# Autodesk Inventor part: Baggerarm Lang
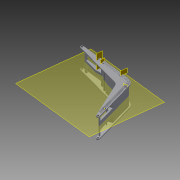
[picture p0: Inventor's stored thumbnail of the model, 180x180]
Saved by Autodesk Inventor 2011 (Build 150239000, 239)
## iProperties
Created: 2011-06
Part Number: Baggerarm Lang
Document SubType Name: Modeling
Designer: Splendor
Density: 1 g/cm^3
Author: Splendor
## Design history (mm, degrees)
sketch "Skizze1"
  geometry: L1 (-226.92, -104.915)-(-3257.541, 6449.975); L2 (240.687, 67.601)-(-1916.665, 7748.673); L3 (-3149.923, 8798.534)-(-12577.464, 9873.179); L4 (-12671.494, 9383.579)-(-3901.21, 6994.175); A1 r 250 centre (0, 0) between (-226.92, -104.915) and (240.687, 67.601); A2 r 1451.763 centre (-3314.345, 7356.112) between (-1916.665, 7748.673) and (-3149.923, 8798.534); A3 r 250 centre (-12605.778, 9624.788) between (-12577.464, 9873.179) and (-12671.494, 9383.579); A4 r 998.218 centre (-4163.604, 6031.061) between (-3257.541, 6449.975) and (-3901.21, 6994.175); 1 further point
  constraints: 8 end point, 8 point on circle, 8 tangent, 4 centre point, 1 coincident
  dimensions: "d0" = 500 diameter of A1; "d1" = 500 diameter of A3
extrude "Extrusion1" new body sketch "Skizze1" distance "d2" = 200; taper "d3" = 0 deg
sketch "Skizze2"
  geometry: C1 r 175 at (-12605.778, 9624.788); C2 r 175 at (0, 0); A1 r 250 centre (0, 0) between (-226.92, -104.915) and (240.687, 67.601) reference; A2 r 250 centre (-12605.778, 9624.788) between (-12577.464, 9873.179) and (-12671.494, 9383.579) reference
  constraints: 2 centre point, 2 coincident
  dimensions: "d5" = 350 diameter of C1; "d6" = 350 diameter of C2
extrude "Extrusion2" cut sketch "Skizze2" stored distance "d7" = 200; taper "d8" = 0 deg
workplane "Arbeitsebene1"
mirror "Spiegeln1"
sketch "Skizze3"
  geometry: L1 (-3912.57, -8515.113)-(-159.064, -2345.636) reference; L2 (542.098, -1877.837)-(9526.566, -497.099) reference; L3 (-1344.227, -903.431)-(-4357.63, -8290.747) reference; L4 (8690.156, -200)-(0, -200); L5 (-159.064, -2345.636)-(-3912.57, -8515.113) reference; L6 (9526.566, -497.099)-(542.098, -1877.837) reference; L7 (0, 0)-(9488.592, 0) reference; L8 (-4357.63, -8290.747)-(-1344.227, -903.431) reference; L9 (-1159.042, -978.971)-(-4022.549, -7998.821); L10 (1246.9, -1564.457)-(906.372, -1616.79); L11 (3330.231, -1244.29)-(3545.266, -575.476); L12 (3599.295, -541.195)-(5980.725, -849.981); L13 (1246.9, -1564.457)-(3330.231, -1244.29); L14 (5980.725, -849.981)-(8709.257, -430.658); L15 (-2274.818, -5428.132)-(-2678.095, -5465.687); L16 (-2763.514, -5533.108)-(-3307.777, -7136.248); L17 (-538.042, -2573.468)-(-2274.818, -5428.132); L18 (-3307.777, -7136.248)-(-3878.853, -8074.901); C1 r 175 at (-4126.148, -8385.172) reference; C2 r 175 at (9488.592, -250) reference; A1 r 250 centre (-4126.148, -8385.172) between (-4357.63, -8290.747) and (-3912.57, -8515.113) reference; A2 r 998.218 centre (693.724, -2864.472) between (542.098, -1877.837) and (-159.064, -2345.636) reference; A3 r 250 centre (9488.592, -250) between (9526.566, -497.099) and (9488.592, 0) reference; A4 r 1451.763 centre (0, -1451.763) between (0, 0) and (-1344.227, -903.431) reference; A5 r 1251.763 centre (0, -1451.763) between (0, -200) and (-1159.042, -978.971); A6 r 1265.674 centre (693.724, -2864.472) between (906.372, -1616.79) and (-538.042, -2573.468); A7 r 800 centre (9488.592, -250) between (8690.156, -200) and (8709.257, -430.658); A8 r 400 centre (-4126.148, -8385.172) between (-3877.158, -8072.116) and (-4022.549, -7998.821); A9 r 50 centre (3592.866, -590.78) between (3599.295, -541.195) and (3545.266, -575.476); A10 r 100 centre (-2668.823, -5565.256) between (-2678.095, -5465.687) and (-2763.514, -5533.108)
  constraints: 22 end point, 12 point on circle, 7 parallel, 6 centre point, 5 tangent, 4 coincident, 1 collinear, 1 point on line
  dimensions: "d12" = 200 distance between parallel lines of L7 L4; "d13" = 200 distance between parallel lines of L9 L8; "d16" = 800 radius of A7; "d18" = 100 diameter of A9; "d19" = 200 diameter of A10
extrude "Extrusion3" join sketch "Skizze3" stored distance "d20" = 0; taper "d21" = 0 deg
sketch "Skizze4"
  geometry: L1 (5980.725, -849.981)-(3599.295, -541.195) reference; L2 (3545.266, -575.476)-(3330.231, -1244.29) reference; C1 r 150 at (3805.463, -976.537)
  constraints: 1 centre point
  dimensions: "d22" = 300 diameter of C1
extrude "Extrusion4" join sketch "Skizze4" stored distance "d23" = 200; taper "d24" = 0 deg
sketch "Skizze5"
  geometry: C1 r 75 at (-2558.636, -5694.936)
  constraints: 1 centre point
  dimensions: "d25" = 150 diameter of C1
extrude "Extrusion5" join sketch "Skizze5" stored distance "d26" = 200; taper "d27" = 0 deg
sketch "Skizze6"
  geometry: L1 (0, -7581.422)-(3400, -7581.422) reference; L2 (3400, -7581.422)-(2400, -7581.422); L3 (2400, -7581.422)-(2400, -4081.422); L4 (2400, -4081.422)-(3400, -4081.422); L5 (3400, -4081.422)-(3400, -7581.422); L6 (0, -7581.422)-(1000, -7581.422); L7 (1000, -7581.422)-(1000, -4081.422); L8 (1000, -4081.422)-(0, -4081.422); L9 (0, -4081.422)-(0, -7581.422); 1 further point
  constraints: 16 end point, 4 parallel, 2 horizontal, 2 perpendicular
  dimensions: "d28" = 1000 distance of L7.end L8.end; "d29" = 1000 distance of L3.end L4.end; "d30" = 3500 distance between parallel lines of L1 L8; "d31" = 3500 distance of L2.end L3.end
extrude "Extrusion6" cut sketch "Skizze6" stored distance "d32" = 10; taper "d33" = 0 deg
sketch "Skizze7"
  geometry: L1 (0, 3400)-(3800, 3400); L2 (3800, 3400)-(3800, 2100); L3 (3800, 2100)-(0, 2100); L4 (0, 2100)-(0, 3400); L5 (0, 0)-(3800, 0); L6 (3800, 0)-(3800, 1300); L7 (3800, 1300)-(0, 1300); L8 (0, 1300)-(0, 0); 1 further point
  constraints: 16 end point, 4 parallel, 2 horizontal, 2 perpendicular
  dimensions: "d34" = 1300 distance of L1.end L2.end; "d35" = 1300 distance of L5.end L6.end; "d36" = 3800 distance of L2.end L3.end; "d37" = 3800 distance of L6.end L7.end
extrude "Extrusion7" cut sketch "Skizze7" stored distance "d38" = 10; taper "d39" = 0 deg
sketch "Skizze8"
  geometry: L1 (-155.45, 368.558)-(-217.437, 351.148) reference; L2 (-671.657, 1333.574)-(-217.437, 351.148) reference; L3 (-1030.851, 2988.04)-(-671.657, 1333.574) reference; L4 (-1504.514, 3147.69)-(-1108.085, 3064.702) reference; L5 (-1699.867, 3570.214)-(-1504.514, 3147.69) reference; L6 (-1005.586, 3765.214)-(-1699.867, 3570.214) reference; L7 (-59.175, 395.599)-(-1005.586, 3765.214) reference; L8 (-211.932, 339.241)-(-275.382, 476.476); L9 (-59.175, 395.599)-(-100.058, 541.159); A1 r 400 centre (0, 0) between (-155.45, 368.558) and (-211.932, 339.241) reference; A2 r 400 centre (0, 0) between (-59.175, 395.599) and (-211.932, 339.241); A3 r 550.332 centre (0, 0) between (-100.058, 541.159) and (-275.382, 476.476); A4 r 400 centre (0, 0) between (-59.175, 395.599) and (-155.45, 368.558) reference; A5 r 100 centre (-1128.575, 2966.824) between (-1030.851, 2988.04) and (-1108.085, 3064.702) reference
  constraints: 5 point on circle, 4 end point, 4 point on line, 2 centre point, 2 coincident
extrude "Extrusion8" join sketch "Skizze8" stored distance "d40" = 10; taper "d41" = 0 deg
sketch "Skizze9"
  geometry: L1 (-8031.267, 9153.663)-(-11806.816, 9584.038) reference; L2 (-8031.267, 9153.663)-(-8088.866, 8648.362) reference; L3 (-9188.433, 8631.378)-(-8088.866, 8648.362) reference; L4 (-11833.273, 9351.947)-(-9188.433, 8631.378) reference; L5 (-11818.142, 9484.681)-(-11833.273, 9351.947) reference; L6 (-11851.918, 9357.027)-(-11496.339, 9260.152); L7 (-11806.816, 9584.038)-(-11440.869, 9542.324); A1 r 800 centre (-12605.778, 9624.788) between (-11818.142, 9484.681) and (-11806.816, 9584.038) reference; A2 r 800 centre (-12605.778, 9624.788) between (-11851.918, 9357.027) and (-11806.816, 9584.038); A3 r 1167.824 centre (-12605.778, 9624.788) between (-11496.339, 9260.152) and (-11440.869, 9542.324)
  constraints: 4 end point, 4 point on circle, 4 point on line, 2 centre point, 2 coincident, 1 concentric
extrude "Extrusion9" join sketch "Skizze9" stored distance "d42" = 10; taper "d43" = 0 deg
workplane "Arbeitsebene2"
sketch "Skizze12"
  geometry: L1 (13846.222, -8290.747)-(10832.82, -903.431) reference; L2 (9488.592, 0)-(0, 0) reference; L3 (-37.974, -497.099)-(8946.495, -1877.837) reference; L4 (9647.657, -2345.636)-(13401.163, -8515.113) reference; L5 (3651.387, -150)-(9488.592, -150); L6 (3651.387, -300)-(9488.592, -300); L7 (3651.387, -450)-(9488.592, -450); L8 (13481.501, -7793.778)-(10693.93, -960.086); L9 (13342.612, -7850.433)-(10555.041, -1016.741); L10 (13203.723, -7907.088)-(10416.152, -1073.396); L11 (12882.87, -8037.969)-(14197.995, -7501.508); C1 r 175 at (13614.74, -8385.172) reference; C2 r 175 at (0, -250) reference; A1 r 250 centre (13614.74, -8385.172) between (13401.163, -8515.113) and (13846.222, -8290.747) reference; A2 r 1451.763 centre (9488.592, -1451.763) between (10832.82, -903.431) and (9488.592, 0) reference; A3 r 250 centre (0, -250) between (0, 0) and (-37.974, -497.099) reference; A4 r 998.218 centre (8794.868, -2864.472) between (9647.657, -2345.636) and (8946.495, -1877.837) reference; A5 r 1301.763 centre (9488.592, -1451.763) between (10693.93, -960.086) and (9488.592, -150); A6 r 1151.763 centre (9488.592, -1451.763) between (10555.041, -1016.741) and (9488.592, -300); A7 r 1001.763 centre (9488.592, -1451.763) between (10416.152, -1073.396) and (9488.592, -450); 1 further point
  constraints: 14 end point, 6 parallel, 6 point on circle, 6 tangent, 3 centre point, 3 coincident, 3 point on line, 1 perpendicular
  dimensions: "d49" = 150 distance between parallel lines of L2 L5; "d50" = 150 distance between parallel lines of L5 L6; "d51" = 150 distance between parallel lines of L6 L7; "d62" = 600 distance of L9.start point (13614.74, -8385.172)
  node "Projizierte Kontur5"
workplane "Arbeitsebene4"
sketch "Skizze14"
  geometry: C1 r 55 at (1650, 50); C2 r 55 at (1650, -100); C3 r 55 at (1650, -250); 4 further points
  constraints: 3 centre point, 3 coincident
  dimensions: "d57" = 110 diameter of C1; "d58" = 110 diameter of C2; "d59" = 110 diameter of C3
feature "Sweeping1" sketch "Skizze14" dims "d60" = 0
workplane "Arbeitsebene5"
mirror "Spiegeln2"
workplane "Arbeitsebene6"
workplane "Arbeitsebene7"
sketch "Skizze15"
  geometry: L1 (-150, -8060.172)-(-150, -8410.172) reference; L2 (-150, 75)-(-150, -275) reference; L3 (-150, -8365.113)-(-150, -8140.747) reference; L4 (-150, -8140.747)-(-150, -753.431) reference; L5 (-150, -753.431)-(-150, 150) reference; L6 (-150, 150)-(-150, -347.099) reference; L7 (-150, -347.099)-(-150, -1727.837) reference; L8 (-150, -1727.837)-(-150, -2195.636) reference; L9 (-150, -2195.636)-(-150, -8365.113) reference; L10 (-150, 80)-(0, 80); L11 (0, -380)-(-150, -380); L12 (-150, -380)-(-150, 80); C1 r 55 at (0, 0) reference; C2 r 55 at (0, -150) reference; C3 r 55 at (0, -300) reference; A1 r 80 centre (0, 0) between (27.839, -75) and (0, 80); A2 r 80 centre (0, -150) between (27.839, -225) and (27.839, -75); A3 r 80 centre (0, -300) between (0, -380) and (27.839, -225); 1 further point
  constraints: 6 end point, 6 point on circle, 3 centre point, 3 coincident, 2 tangent, 1 horizontal, 1 parallel, 1 point on line
  dimensions: "d65" = 160 diameter of A1; "d66" = 160 diameter of A2; "d67" = 160 diameter of A3
extrude "Extrusion11" join sketch "Skizze15" distance "d68" = 200; taper "d69" = 0 deg
sketch "Skizze16"
  geometry: L1 (-150, 380)-(0, 380) reference; L2 (-150, -80)-(-150, 380) reference; L3 (0, -80)-(-150, -80) reference; L4 (0, 380)-(-150, 380); L5 (-150, 380)-(-150, -80); L6 (-150, -80)-(0, -80); C1 r 55 at (0, 0) reference; C2 r 55 at (0, 150) reference; C3 r 55 at (0, 300) reference; C4 r 55 at (0, 300) reference; C5 r 55 at (0, 150) reference; C6 r 55 at (0, 0) reference; C7 r 55 at (0, 150) reference; C8 r 55 at (0, 300) reference; A1 r 80 centre (0, 0) between (0, -80) and (27.839, 75) reference; A2 r 80 centre (0, 150) between (27.839, 75) and (27.839, 225) reference; A3 r 80 centre (0, 300) between (27.839, 225) and (0, 380) reference; A4 r 80 centre (0, 300) between (27.839, 225) and (0, 380); A5 r 80 centre (0, 150) between (27.839, 75) and (27.839, 225); A6 r 80 centre (0, 0) between (0, -80) and (27.839, 75); 1 further point
  constraints: 9 point on circle, 6 end point, 4 tangent, 3 centre point, 3 coincident, 3 collinear, 3 concentric, 1 point on line
extrude "Extrusion12" join sketch "Skizze16" distance "d70" = 200; taper "d71" = 0 deg
workplane "Arbeitsebene8"
workplane "Arbeitsebene9"
sketch "Skizze17"
  geometry: L1 (-1890.983, -150)-(-1705.798, -150) reference; L2 (-1705.798, -150)-(-1879.54, -150) reference; L3 (-1879.54, -150)-(-2064.726, -150) reference; L4 (-2064.726, -150)-(-1890.983, -150) reference; L5 (-5258.773, -150)-(-5073.587, -150) reference; L6 (-5073.587, -150)-(-5247.33, -150) reference; L7 (-5247.33, -150)-(-5432.515, -150) reference; L8 (-5432.515, -150)-(-5258.773, -150) reference; L9 (-275, -150)-(75, -150) reference; L10 (-9808.607, -150)-(-9458.607, -150) reference; L11 (-346.836, -150)-(150, -150) reference; L12 (150, -150)-(-753.431, -150) reference; L13 (-753.431, -150)-(-9539.182, -150) reference; L14 (-9539.182, -150)-(-9762.098, -150) reference; L15 (-9762.098, -150)-(-1964.634, -150) reference; L16 (-1964.634, -150)-(-1492.097, -150) reference; L17 (-1492.097, -150)-(-346.836, -150) reference; L18 (-380, -150)-(80, -150); L19 (80, -150)-(80, 0); L20 (-380, 0)-(-380, -150); C1 r 55 at (-300, 0) reference; C2 r 55 at (-150, 0) reference; C3 r 55 at (0, 0) reference; A1 r 80 centre (-300, 0) between (-225, 27.839) and (-380, 0); A2 r 80 centre (-150, 0) between (-75, 27.839) and (-225, 27.839); A3 r 80 centre (0, 0) between (80, 0) and (-75, 27.839); 1 further point
  constraints: 6 end point, 6 point on circle, 3 centre point, 3 coincident, 2 tangent, 1 horizontal, 1 parallel, 1 perpendicular, 1 point on line
  dimensions: "d74" = 160 diameter of A1; "d75" = 160 diameter of A2; "d76" = 160 diameter of A3
extrude "Extrusion13" join sketch "Skizze17" distance "d77" = 200; taper "d78" = 0 deg
sketch "Skizze18"
  geometry: L1 (-380, -150)-(-380, 0) reference; L2 (80, -150)-(-380, -150) reference; L3 (80, 0)-(80, -150) reference; L4 (-380, 0)-(-380, -150); L5 (-380, -150)-(80, -150); L6 (80, -150)-(80, 0); C1 r 55 at (0, 0) reference; C2 r 55 at (-150, 0) reference; C3 r 55 at (-300, 0) reference; A1 r 80 centre (0, 0) between (80, 0) and (-75, 27.839) reference; A2 r 80 centre (-150, 0) between (-75, 27.839) and (-225, 27.839) reference; A3 r 80 centre (-300, 0) between (-225, 27.839) and (-380, 0) reference; A4 r 80 centre (-300, 0) between (-225, 27.839) and (-380, 0); A5 r 80 centre (-150, 0) between (-75, 27.839) and (-225, 27.839); A6 r 80 centre (0, 0) between (80, 0) and (-75, 27.839); 1 further point
  constraints: 6 end point, 6 point on circle, 4 tangent, 3 centre point, 3 coincident, 3 collinear, 2 concentric, 1 point on line
extrude "Extrusion14" join sketch "Skizze18" distance "d79" = 200; taper "d80" = 0 deg
node "Volumenkörper1"
node "Projizierte Kontur1"
node "Projizierte Kontur2"
node "Projizierte Kontur3"
node "Projizierte Kontur7"
node "Projizierte Kontur8"
node "Projizierte Kontur9"
node "Projizierte Kontur10"
node "Projizierte Kontur11"
node "Projizierte Kontur12"
other parameters: "d56" = 947.04923, "d63" = -4837.20539, "d73" = -6978.285
